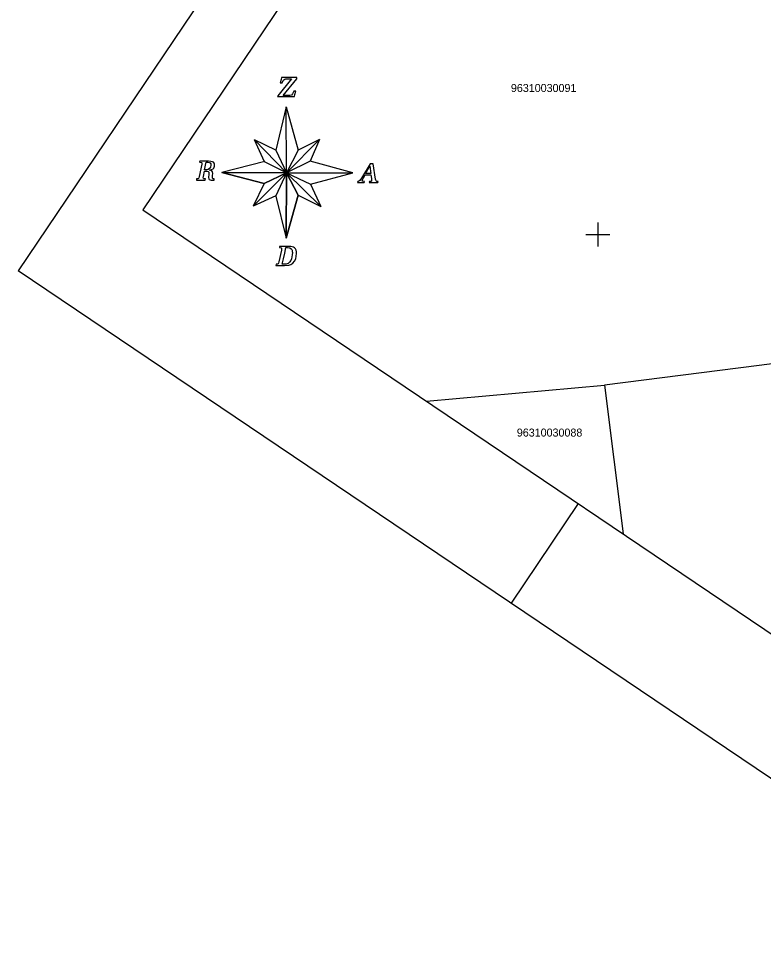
# Model space of a CAD drawing. Extents: x 562228 to 562468, y 414712 to 414970.
# Drawn here: x 562227.6 to 562320.7, y 414712.5 to 414827 of the extents above; entities that cross this region are included whole.
import ezdxf

# ---------------------------------------------------------------- set-up
doc = ezdxf.new("R2010")
doc.units = 0
for name, color, linetype in [('GEOD_ELEM_####_####_#', 7, 'Continuous'), ('RAMI_PLAN_####_TKST_#', 7, 'Continuous'), ('ROBZ_UZMR_####_####_#', 7, 'Continuous'), ('ROBZ_UZMR_####_TKST_#', 7, 'Continuous')]:
    doc.layers.add(name, color=color, linetype=linetype)

msp = doc.modelspace()

# ---------------------------------------------------------------- linework, layer by layer
at = {"layer": 'GEOD_ELEM_####_####_#'}
for p, q in [((562300, 414801.5), (562300, 414800)), ((562298.5, 414800), (562300, 414800)), ((562300, 414800), (562300, 414798.5)), ((562300, 414800), (562301.5, 414800))]:
    msp.add_line(p, q, dxfattribs=at)
at = {"layer": 'RAMI_PLAN_####_TKST_#'}
for p, q in [((562345.01, 414969.6), (562227.59, 414795.49)), ((562261.72, 414819.46), (562260.01, 414817.34)), ((562260.42, 414819.39), (562260.3, 414818.94)), ((562260.3, 414818.94), (562260.55, 414818.94)), ((562260.47, 414819.6), (562260.42, 414819.39)), ((562262.4, 414819.6), (562260.47, 414819.6)), ((562260.55, 414818.94), (562260.68, 414819.25)), ((562260.68, 414817.38), (562262.38, 414819.47)), ((562260.68, 414819.25), (562260.76, 414819.34)), ((562260.76, 414819.34), (562260.87, 414819.41)), ((562260.87, 414819.41), (562260.99, 414819.44)), ((562260.99, 414819.44), (562261.15, 414819.46)), ((562261.15, 414819.46), (562261.72, 414819.46)), ((562262.38, 414819.47), (562262.4, 414819.6)), ((562261.84, 414817.56), (562261.7, 414817.42)), ((562261.97, 414817.81), (562261.84, 414817.56)), ((562262, 414817.9), (562261.97, 414817.81)), ((562262.25, 414817.9), (562262, 414817.9)), ((562262.14, 414817.49), (562262.25, 414817.9)), ((562260.01, 414817.34), (562259.99, 414817.23)), ((562259.99, 414817.23), (562262.08, 414817.23)), ((562261.23, 414817.38), (562260.68, 414817.38)), ((562261.53, 414817.39), (562261.23, 414817.38)), ((562261.7, 414817.42), (562261.53, 414817.39)), ((562262.08, 414817.23), (562262.14, 414817.49)), ((562265.22, 414811.89), (562262.57, 414810.53)), ((562250.51, 414808.78), (562250.19, 414807.26)), ((562250.27, 414809.17), (562250.24, 414809.03)), ((562250.24, 414809.03), (562250.3, 414809.03)), ((562250.83, 414809.17), (562250.27, 414809.17)), ((562250.3, 414809.03), (562250.48, 414809.01)), ((562250.48, 414809.01), (562250.51, 414808.97)), ((562250.51, 414808.97), (562250.52, 414808.89)), ((562250.52, 414808.89), (562250.51, 414808.78)), ((562251.34, 414809.17), (562250.83, 414809.17)), ((562250.86, 414808.08), (562251.07, 414809.03)), ((562251.07, 414809.03), (562251.25, 414809.03)), ((562251.25, 414809.03), (562251.43, 414809.01)), ((562251.65, 414809.15), (562251.34, 414809.17)), ((562251.43, 414809.01), (562251.55, 414808.96)), ((562251.6, 414808.44), (562251.49, 414808.25)), ((562251.55, 414808.96), (562251.62, 414808.85)), ((562251.64, 414808.67), (562251.6, 414808.44)), ((562251.62, 414808.85), (562251.64, 414808.67)), ((562251.86, 414809.1), (562251.65, 414809.15)), ((562251.97, 414809.03), (562251.86, 414809.1)), ((562252.05, 414808.94), (562251.97, 414809.03)), ((562252.01, 414808.31), (562252.07, 414808.42)), ((562252.1, 414808.82), (562252.05, 414808.94)), ((562252.07, 414808.42), (562252.1, 414808.54)), ((562252.11, 414808.67), (562252.1, 414808.82)), ((562252.1, 414808.54), (562252.11, 414808.67)), ((562258.4, 414809.13), (562253.03, 414807.77)), ((562271.53, 414808.85), (562270.45, 414807.04)), ((562270.96, 414807.62), (562271.5, 414808.53)), ((562271.5, 414808.53), (562271.65, 414807.62)), ((562271.93, 414808.85), (562271.53, 414808.85)), ((562272.23, 414806.94), (562271.93, 414808.85)), ((562250.19, 414807.26), (562250.14, 414807.08)), ((562250.69, 414807.07), (562250.72, 414807.25)), ((562250.72, 414807.25), (562250.86, 414807.94)), ((562251.13, 414808.08), (562250.86, 414808.08)), ((562250.86, 414807.94), (562251.02, 414807.94)), ((562251.02, 414807.94), (562251.2, 414807.93)), ((562251.32, 414808.13), (562251.13, 414808.08)), ((562251.2, 414807.93), (562251.31, 414807.89)), ((562251.31, 414807.89), (562251.38, 414807.8)), ((562251.49, 414808.25), (562251.32, 414808.13)), ((562251.38, 414807.41), (562251.36, 414807.24)), ((562251.36, 414807.24), (562251.36, 414807.12)), ((562251.38, 414807.8), (562251.4, 414807.65)), ((562251.4, 414807.54), (562251.38, 414807.41)), ((562251.4, 414807.65), (562251.4, 414807.54)), ((562251.47, 414808.06), (562251.73, 414808.12)), ((562251.47, 414808.03), (562251.47, 414808.06)), ((562251.65, 414808.01), (562251.47, 414808.03)), ((562251.78, 414807.95), (562251.65, 414808.01)), ((562251.73, 414808.12), (562251.92, 414808.23)), ((562251.85, 414807.83), (562251.78, 414807.95)), ((562251.83, 414807.14), (562251.85, 414807.37)), ((562251.88, 414807.65), (562251.85, 414807.83)), ((562251.85, 414807.37), (562251.88, 414807.65)), ((562251.92, 414808.23), (562252.01, 414808.31)), ((562253.03, 414807.77), (562261.11, 414807.72)), ((562258.29, 414806.37), (562253.03, 414807.77)), ((562256.94, 414803.56), (562261.11, 414807.72)), ((562261.11, 414807.72), (562258.29, 414806.37)), ((562261.11, 414807.72), (562259.75, 414804.86)), ((562261.05, 414799.55), (562261.11, 414807.72)), ((562261.11, 414807.72), (562262.57, 414804.91)), ((562270.7, 414807.1), (562270.93, 414807.48)), ((562270.93, 414807.48), (562271.65, 414807.48)), ((562271.65, 414807.62), (562270.96, 414807.62)), ((562271.65, 414807.48), (562271.71, 414807.02)), ((562249.87, 414806.95), (562249.84, 414806.81)), ((562249.84, 414806.81), (562250.39, 414806.81)), ((562250.01, 414806.96), (562249.87, 414806.95)), ((562250.09, 414807), (562250.01, 414806.96)), ((562250.14, 414807.08), (562250.09, 414807)), ((562250.39, 414806.81), (562250.95, 414806.81)), ((562250.71, 414807.01), (562250.69, 414807.07)), ((562250.75, 414806.97), (562250.71, 414807.01)), ((562250.98, 414806.95), (562250.75, 414806.97)), ((562250.95, 414806.81), (562250.98, 414806.95)), ((562251.36, 414807.12), (562251.38, 414806.97)), ((562251.38, 414806.97), (562251.44, 414806.88)), ((562251.44, 414806.88), (562251.55, 414806.82)), ((562251.55, 414806.82), (562251.7, 414806.81)), ((562251.7, 414806.81), (562252.04, 414806.81)), ((562251.84, 414807.05), (562251.83, 414807.14)), ((562251.87, 414806.99), (562251.84, 414807.05)), ((562251.94, 414806.96), (562251.87, 414806.99)), ((562252.07, 414806.95), (562251.94, 414806.96)), ((562252.04, 414806.81), (562252.07, 414806.95)), ((562258.29, 414806.37), (562256.94, 414803.56)), ((562269.99, 414806.63), (562269.96, 414806.49)), ((562269.96, 414806.49), (562270.38, 414806.49)), ((562270.15, 414806.66), (562269.99, 414806.63)), ((562270.27, 414806.76), (562270.15, 414806.66)), ((562270.45, 414807.04), (562270.27, 414806.76)), ((562270.38, 414806.49), (562270.81, 414806.49)), ((562270.54, 414806.75), (562270.61, 414806.94)), ((562270.56, 414806.69), (562270.54, 414806.75)), ((562270.61, 414806.66), (562270.56, 414806.69)), ((562270.61, 414806.94), (562270.7, 414807.1)), ((562270.84, 414806.63), (562270.61, 414806.66)), ((562270.81, 414806.49), (562270.84, 414806.63)), ((562271.45, 414806.63), (562271.42, 414806.49)), ((562271.42, 414806.49), (562271.97, 414806.49)), ((562271.64, 414806.64), (562271.45, 414806.63)), ((562271.71, 414806.69), (562271.64, 414806.64)), ((562271.71, 414807.02), (562271.73, 414806.88)), ((562271.73, 414806.77), (562271.71, 414806.69)), ((562271.73, 414806.88), (562271.73, 414806.77)), ((562271.97, 414806.49), (562272.52, 414806.49)), ((562272.26, 414806.8), (562272.23, 414806.94)), ((562272.3, 414806.71), (562272.26, 414806.8)), ((562272.4, 414806.65), (562272.3, 414806.71)), ((562272.55, 414806.63), (562272.4, 414806.65)), ((562272.52, 414806.49), (562272.55, 414806.63)), ((562259.75, 414804.86), (562256.94, 414803.56)), ((562259.75, 414804.81), (562261.05, 414799.55)), ((562262.57, 414804.91), (562261.05, 414799.55)), ((562260.45, 414798.07), (562260.13, 414796.61)), ((562260.23, 414798.52), (562260.2, 414798.38)), ((562260.2, 414798.38), (562260.43, 414798.36)), ((562260.77, 414798.52), (562260.23, 414798.52)), ((562260.43, 414798.36), (562260.47, 414798.32)), ((562260.48, 414798.17), (562260.45, 414798.07)), ((562260.47, 414798.32), (562260.48, 414798.25)), ((562260.48, 414798.25), (562260.48, 414798.17)), ((562261.39, 414798.52), (562260.77, 414798.52)), ((562260.87, 414797.69), (562261.03, 414798.38)), ((562261.03, 414798.38), (562261.2, 414798.38)), ((562261.2, 414798.38), (562261.49, 414798.34)), ((562261.62, 414798.51), (562261.39, 414798.52)), ((562261.49, 414798.34), (562261.68, 414798.23)), ((562261.82, 414798.47), (562261.62, 414798.51)), ((562261.68, 414798.23), (562261.75, 414798.15)), ((562261.75, 414798.15), (562261.79, 414798.04)), ((562261.98, 414798.42), (562261.82, 414798.47)), ((562262.11, 414798.34), (562261.98, 414798.42)), ((562262.22, 414798.22), (562262.11, 414798.34)), ((562262.29, 414798.06), (562262.22, 414798.22)), ((562262.34, 414797.87), (562262.29, 414798.06)), ((562260.57, 414796.3), (562260.72, 414796.99)), ((562260.72, 414796.99), (562260.87, 414797.69)), ((562261.71, 414796.97), (562261.62, 414796.77)), ((562261.78, 414797.21), (562261.71, 414796.97)), ((562261.82, 414797.47), (562261.78, 414797.21)), ((562261.79, 414798.04), (562261.82, 414797.91)), ((562261.82, 414797.91), (562261.83, 414797.76)), ((562261.83, 414797.76), (562261.82, 414797.47)), ((562262.08, 414796.67), (562262.24, 414796.98)), ((562262.24, 414796.98), (562262.32, 414797.3)), ((562262.32, 414797.3), (562262.35, 414797.64)), ((562262.35, 414797.64), (562262.34, 414797.87)), ((562259.79, 414796.3), (562259.76, 414796.16)), ((562259.76, 414796.16), (562260.32, 414796.16)), ((562259.95, 414796.31), (562259.79, 414796.3)), ((562260.04, 414796.34), (562259.95, 414796.31)), ((562260.08, 414796.43), (562260.04, 414796.34)), ((562260.13, 414796.61), (562260.08, 414796.43)), ((562260.32, 414796.16), (562260.84, 414796.16)), ((562260.82, 414796.3), (562260.57, 414796.3)), ((562261.07, 414796.33), (562260.82, 414796.3)), ((562260.84, 414796.16), (562261.39, 414796.19)), ((562261.29, 414796.41), (562261.07, 414796.33)), ((562261.47, 414796.56), (562261.29, 414796.41)), ((562261.39, 414796.19), (562261.65, 414796.27)), ((562261.62, 414796.77), (562261.47, 414796.56)), ((562261.65, 414796.27), (562261.87, 414796.42)), ((562261.87, 414796.42), (562262.08, 414796.67)), ((562350.71, 414712.46), (562227.59, 414795.49)), ((562297.54, 414766.41), (562289.15, 414753.97))]:
    msp.add_line(p, q, dxfattribs=at)
for points in [[(562458.44, 414884.06), (562347.98, 414958.55), (562243.14, 414803.09), (562353.61, 414728.6)], [(562261.05, 414815.95), (562259.75, 414810.53), (562261.11, 414807.72)], [(562269.39, 414807.72), (562264.03, 414809.18), (562261.11, 414807.72)], [(562253.03, 414807.77), (562258.29, 414806.37), (562261.11, 414807.72)], [(562261.11, 414807.72), (562261.05, 414799.55), (562262.57, 414804.91)]]:
    msp.add_lwpolyline(points, close=True, dxfattribs=at)
for points in [[(562261.05, 414815.95), (562262.57, 414810.53), (562261.11, 414807.72), (562261.05, 414815.95), (562259.75, 414810.53), (562261.11, 414807.72)], [(562259.75, 414810.53), (562257.09, 414811.83), (562261.11, 414807.72), (562258.34, 414809.07), (562257.09, 414811.83)], [(562261.11, 414807.72), (562265.22, 414811.89), (562264.03, 414809.18)], [(562264.08, 414806.32), (562269.39, 414807.72), (562264.03, 414809.18), (562261.11, 414807.72), (562269.39, 414807.72)], [(562262.57, 414804.91), (562265.38, 414803.51), (562261.11, 414807.72), (562264.08, 414806.32), (562265.38, 414803.51)]]:
    msp.add_lwpolyline(points, dxfattribs=at)
at = {"layer": 'ROBZ_UZMR_####_####_#'}
for p, q in [((562351.54, 414787.65), (562320.15, 414783.67)), ((562320.15, 414783.67), (562300.84, 414781.22)), ((562278.59, 414779.19), (562300.84, 414781.22)), ((562300.84, 414781.22), (562303.16, 414762.62))]:
    msp.add_line(p, q, dxfattribs=at)

# ---------------------------------------------------------------- texts
at = {"layer": 'ROBZ_UZMR_####_TKST_#'}
for s, p in [('96310030091', (562289.13, 414817.81)), ('96310030088', (562289.87, 414774.78))]:
    msp.add_text(s, height=1, dxfattribs=at).set_placement(p)

doc.saveas('drawing.dxf')
